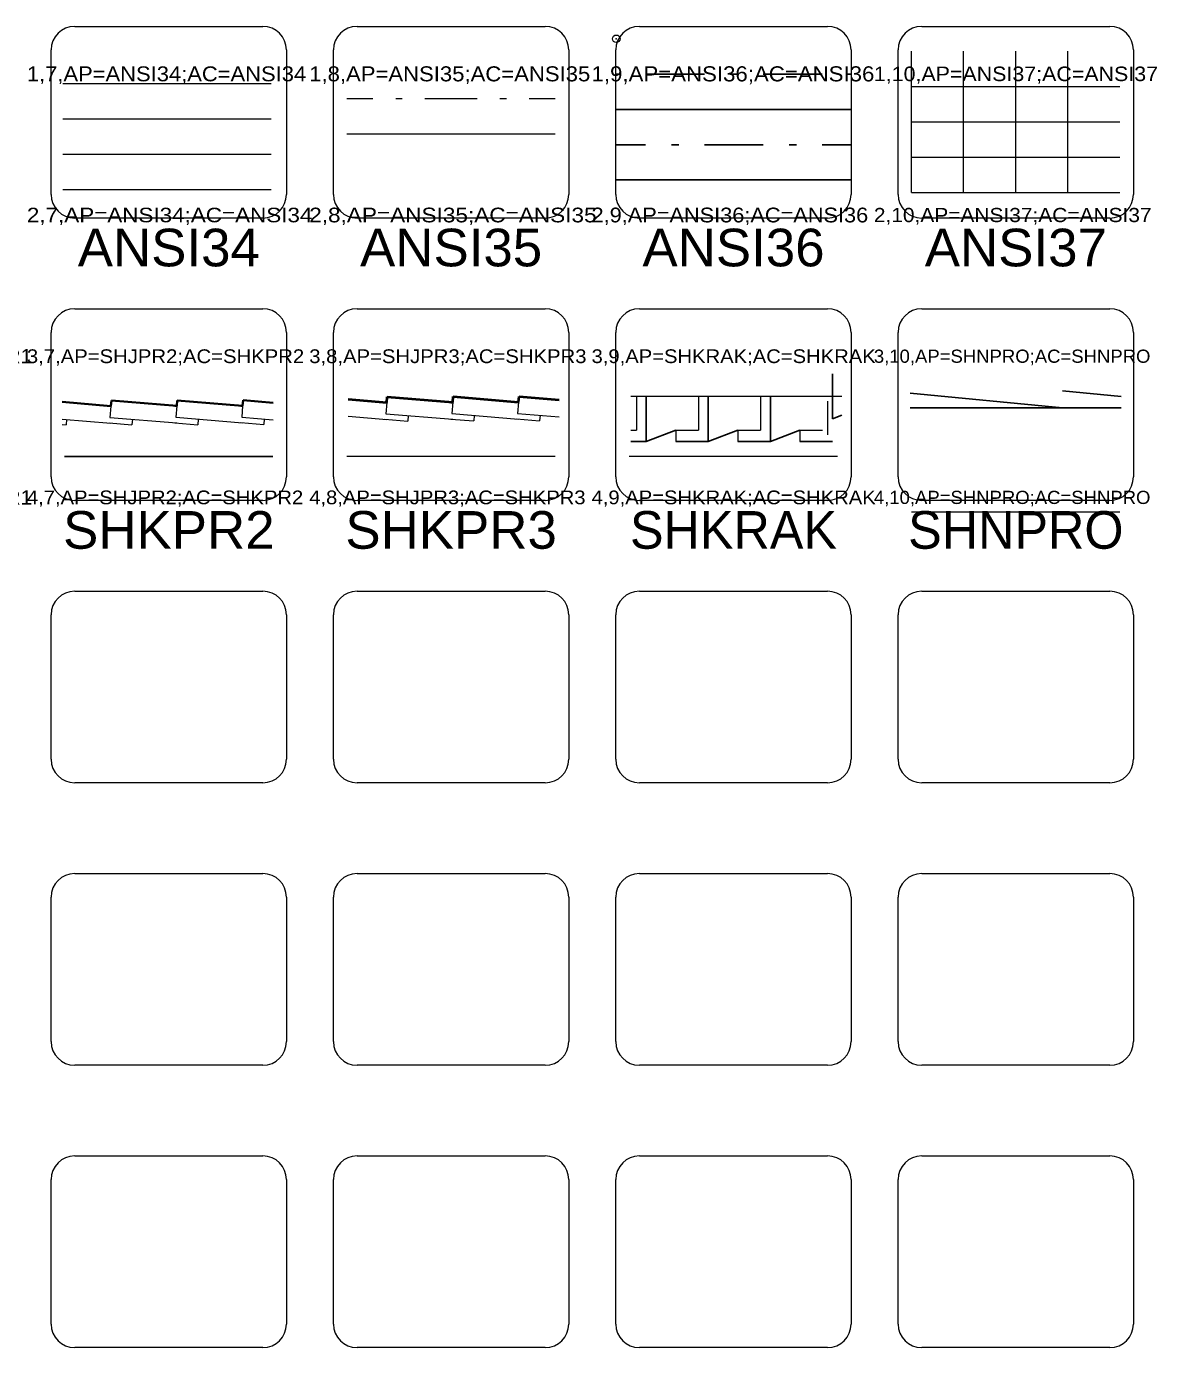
# Model space of a CAD drawing. Extents: x 95935 to 95946.4, y 95971.2 to 95974.7.
# Drawn here: x 95938.633 to 95941.029, y 95971.925 to 95974.732 of the extents above; entities that cross this region are included whole.
import ezdxf
from ezdxf.enums import TextEntityAlignment as Align

# ---------------------------------------------------------------- set-up
doc = ezdxf.new("R2010")
doc.units = 0
doc.header["$LTSCALE"] = 0.032
doc.header["$PDMODE"] = 32
doc.header["$PDSIZE"] = 0.016
for name, color, linetype, lineweight in [('1', 7, 'Continuous', 13), ('25', 7, 'Continuous', 13), ('6', 7, 'Continuous', 13), ('63', 7, 'Continuous', 13)]:
    doc.layers.add(name, color=color, linetype=linetype, lineweight=lineweight)
doc.layers.add('20', color=7, linetype='Continuous')

msp = doc.modelspace()

# ---------------------------------------------------------------- linework, layer by layer
at = {"layer": '1'}
for p, q in [((95938.7357, 95974.7318), (95939.1357, 95974.7318)), ((95939.3357, 95974.7318), (95939.7357, 95974.7318)), ((95939.9357, 95974.7318), (95940.3357, 95974.7318)), ((95940.5357, 95974.7318), (95940.9357, 95974.7318)), ((95938.6857, 95974.3747), (95938.6857, 95974.6818)), ((95939.1857, 95974.6818), (95939.1857, 95974.3747)), ((95939.2857, 95974.3747), (95939.2857, 95974.6818)), ((95939.7857, 95974.6818), (95939.7857, 95974.3747)), ((95939.8857, 95974.3747), (95939.8857, 95974.6818)), ((95940.3857, 95974.6818), (95940.3857, 95974.3747)), ((95940.4857, 95974.3747), (95940.4857, 95974.6818)), ((95940.9857, 95974.6818), (95940.9857, 95974.3747)), ((95939.1357, 95974.3247), (95938.7357, 95974.3247)), ((95939.7357, 95974.3247), (95939.3357, 95974.3247)), ((95940.3357, 95974.3247), (95939.9357, 95974.3247)), ((95940.9357, 95974.3247), (95940.5357, 95974.3247)), ((95938.7357, 95974.1318), (95939.1357, 95974.1318)), ((95939.3357, 95974.1318), (95939.7357, 95974.1318)), ((95939.9357, 95974.1318), (95940.3357, 95974.1318)), ((95940.5357, 95974.1318), (95940.9357, 95974.1318)), ((95938.6857, 95973.7747), (95938.6857, 95974.0818)), ((95939.1857, 95974.0818), (95939.1857, 95973.7747)), ((95939.2857, 95973.7747), (95939.2857, 95974.0818)), ((95939.7857, 95974.0818), (95939.7857, 95973.7747)), ((95939.8857, 95973.7747), (95939.8857, 95974.0818)), ((95940.3857, 95974.0818), (95940.3857, 95973.7747)), ((95940.4857, 95973.7747), (95940.4857, 95974.0818)), ((95940.9857, 95974.0818), (95940.9857, 95973.7747)), ((95939.1357, 95973.7247), (95938.7357, 95973.7247)), ((95939.7357, 95973.7247), (95939.3357, 95973.7247)), ((95940.3357, 95973.7247), (95939.9357, 95973.7247)), ((95940.9357, 95973.7247), (95940.5357, 95973.7247)), ((95938.7357, 95973.5318), (95939.1357, 95973.5318)), ((95939.3357, 95973.5318), (95939.7357, 95973.5318)), ((95939.9357, 95973.5318), (95940.3357, 95973.5318)), ((95940.5357, 95973.5318), (95940.9357, 95973.5318)), ((95938.6857, 95973.1747), (95938.6857, 95973.4818)), ((95939.1857, 95973.4818), (95939.1857, 95973.1747)), ((95939.2857, 95973.1747), (95939.2857, 95973.4818)), ((95939.7857, 95973.4818), (95939.7857, 95973.1747)), ((95939.8857, 95973.1747), (95939.8857, 95973.4818)), ((95940.3857, 95973.4818), (95940.3857, 95973.1747)), ((95940.4857, 95973.1747), (95940.4857, 95973.4818)), ((95940.9857, 95973.4818), (95940.9857, 95973.1747)), ((95939.1357, 95973.1247), (95938.7357, 95973.1247)), ((95939.7357, 95973.1247), (95939.3357, 95973.1247)), ((95940.3357, 95973.1247), (95939.9357, 95973.1247)), ((95940.9357, 95973.1247), (95940.5357, 95973.1247)), ((95938.7357, 95972.9318), (95939.1357, 95972.9318)), ((95939.3357, 95972.9318), (95939.7357, 95972.9318)), ((95939.9357, 95972.9318), (95940.3357, 95972.9318)), ((95940.5357, 95972.9318), (95940.9357, 95972.9318)), ((95938.6857, 95972.5747), (95938.6857, 95972.8818)), ((95939.1857, 95972.8818), (95939.1857, 95972.5747)), ((95939.2857, 95972.5747), (95939.2857, 95972.8818)), ((95939.7857, 95972.8818), (95939.7857, 95972.5747)), ((95939.8857, 95972.5747), (95939.8857, 95972.8818)), ((95940.3857, 95972.8818), (95940.3857, 95972.5747)), ((95940.4857, 95972.5747), (95940.4857, 95972.8818)), ((95940.9857, 95972.8818), (95940.9857, 95972.5747)), ((95939.1357, 95972.5247), (95938.7357, 95972.5247)), ((95939.7357, 95972.5247), (95939.3357, 95972.5247)), ((95940.3357, 95972.5247), (95939.9357, 95972.5247)), ((95940.9357, 95972.5247), (95940.5357, 95972.5247)), ((95938.7357, 95972.3318), (95939.1357, 95972.3318)), ((95939.3357, 95972.3318), (95939.7357, 95972.3318)), ((95939.9357, 95972.3318), (95940.3357, 95972.3318)), ((95940.5357, 95972.3318), (95940.9357, 95972.3318)), ((95938.6857, 95971.9747), (95938.6857, 95972.2818)), ((95939.1857, 95972.2818), (95939.1857, 95971.9747)), ((95939.2857, 95971.9747), (95939.2857, 95972.2818)), ((95939.7857, 95972.2818), (95939.7857, 95971.9747)), ((95939.8857, 95971.9747), (95939.8857, 95972.2818)), ((95940.3857, 95972.2818), (95940.3857, 95971.9747)), ((95940.4857, 95971.9747), (95940.4857, 95972.2818)), ((95940.9857, 95972.2818), (95940.9857, 95971.9747)), ((95939.1357, 95971.9247), (95938.7357, 95971.9247)), ((95939.7357, 95971.9247), (95939.3357, 95971.9247)), ((95940.3357, 95971.9247), (95939.9357, 95971.9247)), ((95940.9357, 95971.9247), (95940.5357, 95971.9247))]:
    msp.add_line(p, q, dxfattribs=at)
for centre, start, end in [((95938.7357, 95974.6818), 90, 180), ((95939.1357, 95974.6818), 0, 90), ((95939.3357, 95974.6818), 90, 180), ((95939.7357, 95974.6818), 0, 90), ((95939.9357, 95974.6818), 90, 180), ((95940.3357, 95974.6818), 0, 90), ((95940.5357, 95974.6818), 90, 180), ((95940.9357, 95974.6818), 0, 90), ((95938.7357, 95974.3747), 180, 270), ((95939.1357, 95974.3747), 270, 0), ((95939.3357, 95974.3747), 180, 270), ((95939.7357, 95974.3747), 270, 0), ((95939.9357, 95974.3747), 180, 270), ((95940.3357, 95974.3747), 270, 0), ((95940.5357, 95974.3747), 180, 270), ((95940.9357, 95974.3747), 270, 0), ((95938.7357, 95974.0818), 90, 180), ((95939.1357, 95974.0818), 0, 90), ((95939.3357, 95974.0818), 90, 180), ((95939.7357, 95974.0818), 0, 90), ((95939.9357, 95974.0818), 90, 180), ((95940.3357, 95974.0818), 0, 90), ((95940.5357, 95974.0818), 90, 180), ((95940.9357, 95974.0818), 0, 90), ((95938.7357, 95973.7747), 180, 270), ((95939.1357, 95973.7747), 270, 0), ((95939.3357, 95973.7747), 180, 270), ((95939.7357, 95973.7747), 270, 0), ((95939.9357, 95973.7747), 180, 270), ((95940.3357, 95973.7747), 270, 0), ((95940.5357, 95973.7747), 180, 270), ((95940.9357, 95973.7747), 270, 0), ((95938.7357, 95973.4818), 90, 180), ((95939.1357, 95973.4818), 0, 90), ((95939.3357, 95973.4818), 90, 180), ((95939.7357, 95973.4818), 0, 90), ((95939.9357, 95973.4818), 90, 180), ((95940.3357, 95973.4818), 0, 90), ((95940.5357, 95973.4818), 90, 180), ((95940.9357, 95973.4818), 0, 90), ((95938.7357, 95973.1747), 180, 270), ((95939.1357, 95973.1747), 270, 0), ((95939.3357, 95973.1747), 180, 270), ((95939.7357, 95973.1747), 270, 0), ((95939.9357, 95973.1747), 180, 270), ((95940.3357, 95973.1747), 270, 0), ((95940.5357, 95973.1747), 180, 270), ((95940.9357, 95973.1747), 270, 0), ((95938.7357, 95972.8818), 90, 180), ((95939.1357, 95972.8818), 0, 90), ((95939.3357, 95972.8818), 90, 180), ((95939.7357, 95972.8818), 0, 90), ((95939.9357, 95972.8818), 90, 180), ((95940.3357, 95972.8818), 0, 90), ((95940.5357, 95972.8818), 90, 180), ((95940.9357, 95972.8818), 0, 90), ((95938.7357, 95972.5747), 180, 270), ((95939.1357, 95972.5747), 270, 0), ((95939.3357, 95972.5747), 180, 270), ((95939.7357, 95972.5747), 270, 0), ((95939.9357, 95972.5747), 180, 270), ((95940.3357, 95972.5747), 270, 0), ((95940.5357, 95972.5747), 180, 270), ((95940.9357, 95972.5747), 270, 0), ((95938.7357, 95972.2818), 90, 180), ((95939.1357, 95972.2818), 0, 90), ((95939.3357, 95972.2818), 90, 180), ((95939.7357, 95972.2818), 0, 90), ((95939.9357, 95972.2818), 90, 180), ((95940.3357, 95972.2818), 0, 90), ((95940.5357, 95972.2818), 90, 180), ((95940.9357, 95972.2818), 0, 90), ((95938.7357, 95971.9747), 180, 270), ((95939.1357, 95971.9747), 270, 0), ((95939.3357, 95971.9747), 180, 270), ((95939.7357, 95971.9747), 270, 0), ((95939.9357, 95971.9747), 180, 270), ((95940.3357, 95971.9747), 270, 0), ((95940.5357, 95971.9747), 180, 270), ((95940.9357, 95971.9747), 270, 0)]:
    msp.add_arc(centre, 0.05, start, end, dxfattribs=at)
at = {"layer": '25'}
for p, q in [((95939.1569, 95973.8178), (95938.7141, 95973.8178)), ((95938.7141, 95973.8178), (95939.1569, 95973.8178)), ((95939.7569, 95973.8178), (95939.3141, 95973.8178)), ((95940.3569, 95973.8178), (95939.9141, 95973.8178)), ((95940.9569, 95973.6997), (95940.5141, 95973.6997))]:
    msp.add_line(p, q, dxfattribs=at)
at = {"layer": '6'}
for p, q in [((95940.5141, 95974.379), (95940.5141, 95974.679)), ((95940.6248, 95974.379), (95940.6248, 95974.679)), ((95940.7355, 95974.379), (95940.7355, 95974.679)), ((95940.8462, 95974.379), (95940.8462, 95974.679)), ((95938.7102, 95974.6103), (95939.153, 95974.6103)), ((95940.5141, 95974.604), (95940.9569, 95974.604)), ((95939.3141, 95974.5784), (95939.3694, 95974.5784)), ((95939.4179, 95974.5784), (95939.4317, 95974.5784)), ((95939.4801, 95974.5784), (95939.5908, 95974.5784)), ((95939.6393, 95974.5784), (95939.6531, 95974.5784)), ((95939.7015, 95974.5784), (95939.7569, 95974.5784)), ((95938.7102, 95974.5353), (95939.153, 95974.5353)), ((95940.5141, 95974.529), (95940.9569, 95974.529)), ((95939.3141, 95974.5034), (95939.7569, 95974.5034)), ((95938.7102, 95974.4603), (95939.153, 95974.4603)), ((95940.5141, 95974.454), (95940.9569, 95974.454)), ((95938.7102, 95974.3853), (95939.153, 95974.3853)), ((95940.5141, 95974.379), (95940.9569, 95974.379)), ((95939.9175, 95973.9462), (95940.0133, 95973.9462)), ((95939.9295, 95973.9462), (95939.9295, 95973.8742)), ((95940.0133, 95973.9462), (95940.1451, 95973.9462)), ((95940.0613, 95973.9462), (95940.0613, 95973.8742)), ((95940.1451, 95973.9462), (95940.2769, 95973.9462)), ((95940.1931, 95973.9462), (95940.1931, 95973.8742)), ((95940.2769, 95973.9462), (95940.3662, 95973.9462)), ((95940.3355, 95973.9357), (95940.3355, 95973.8637)), ((95938.8127, 95973.9251), (95938.8107, 95973.9011)), ((95938.9527, 95973.9254), (95938.9507, 95973.9014)), ((95939.0927, 95973.9257), (95939.0907, 95973.9017)), ((95939.399, 95973.933), (95939.397, 95973.909)), ((95939.397, 95973.909), (95939.539, 95973.8972)), ((95939.539, 95973.9333), (95939.537, 95973.9093)), ((95939.537, 95973.9093), (95939.679, 95973.8975)), ((95939.679, 95973.9336), (95939.677, 95973.9096)), ((95939.677, 95973.9096), (95939.7655, 95973.9022)), ((95938.7088, 95973.8976), (95938.8127, 95973.889)), ((95938.7088, 95973.8857), (95938.7174, 95973.885)), ((95938.7184, 95973.8969), (95938.7174, 95973.885)), ((95938.8087, 95973.8893), (95938.8574, 95973.8853)), ((95938.8107, 95973.9011), (95938.9527, 95973.8893)), ((95938.8584, 95973.8972), (95938.8574, 95973.8853)), ((95938.9487, 95973.8896), (95938.9974, 95973.8856)), ((95938.9507, 95973.9014), (95939.0927, 95973.8896)), ((95938.9984, 95973.8975), (95938.9974, 95973.8856)), ((95939.0887, 95973.8899), (95939.1374, 95973.8859)), ((95939.0907, 95973.9017), (95939.1575, 95973.8961)), ((95939.1384, 95973.8978), (95939.1374, 95973.8859)), ((95939.3168, 95973.9037), (95939.399, 95973.8969)), ((95939.395, 95973.8972), (95939.4437, 95973.8932)), ((95939.4447, 95973.9051), (95939.4437, 95973.8932)), ((95939.535, 95973.8975), (95939.5837, 95973.8935)), ((95939.5847, 95973.9054), (95939.5837, 95973.8935)), ((95939.675, 95973.8978), (95939.7237, 95973.8938)), ((95939.7247, 95973.9057), (95939.7237, 95973.8938)), ((95939.9175, 95973.8742), (95939.9295, 95973.8742)), ((95940.0133, 95973.8742), (95940.0613, 95973.8742)), ((95940.0133, 95973.8742), (95940.0133, 95973.8502)), ((95940.1451, 95973.8742), (95940.1931, 95973.8742)), ((95940.1451, 95973.8742), (95940.1451, 95973.8502)), ((95940.2769, 95973.8742), (95940.3249, 95973.8742)), ((95940.2769, 95973.8742), (95940.2769, 95973.8502))]:
    msp.add_line(p, q, dxfattribs=at)
at = {"layer": '6', "lineweight": 25}
for p, q in [((95939.8944, 95974.6305), (95939.8866, 95974.6305)), ((95939.9491, 95974.6305), (95940.0741, 95974.6305)), ((95940.1288, 95974.6305), (95940.1444, 95974.6305)), ((95940.1991, 95974.6305), (95940.3241, 95974.6305)), ((95940.3788, 95974.6305), (95940.3866, 95974.6305)), ((95939.8866, 95974.5555), (95940.3866, 95974.5555)), ((95939.8866, 95974.4805), (95939.9491, 95974.4805)), ((95940.0038, 95974.4805), (95940.0194, 95974.4805)), ((95940.0741, 95974.4805), (95940.1991, 95974.4805)), ((95940.2538, 95974.4805), (95940.2694, 95974.4805)), ((95940.3241, 95974.4805), (95940.3866, 95974.4805)), ((95939.8866, 95974.4055), (95940.3866, 95974.4055)), ((95940.3459, 95973.9937), (95940.3459, 95973.8977)), ((95940.0823, 95973.9462), (95940.0823, 95973.8502)), ((95940.2141, 95973.9462), (95940.2141, 95973.8502)), ((95940.511, 95973.9528), (95940.8349, 95973.9217)), ((95940.8349, 95973.9577), (95940.9597, 95973.9457)), ((95940.511, 95973.9217), (95940.9597, 95973.9217)), ((95940.3459, 95973.8977), (95940.3662, 95973.9055)), ((95940.0823, 95973.8502), (95940.1451, 95973.8742)), ((95940.2141, 95973.8502), (95940.2769, 95973.8742)), ((95939.9175, 95973.8502), (95939.9505, 95973.8502)), ((95940.0133, 95973.8502), (95940.0823, 95973.8502)), ((95940.1451, 95973.8502), (95940.2141, 95973.8502)), ((95940.2769, 95973.8502), (95940.3459, 95973.8502))]:
    msp.add_line(p, q, dxfattribs=at)
at = {"layer": '6', "lineweight": 35}
for p, q in [((95938.8127, 95973.9251), (95938.8137, 95973.937)), ((95938.8137, 95973.937), (95938.9527, 95973.9254)), ((95938.9527, 95973.9254), (95938.9537, 95973.9373)), ((95938.9537, 95973.9373), (95939.0927, 95973.9257)), ((95939.0927, 95973.9257), (95939.0937, 95973.9376)), ((95939.0937, 95973.9376), (95939.1575, 95973.9323)), ((95938.7088, 95973.9338), (95938.8127, 95973.9251)), ((95938.8087, 95973.9254), (95938.8127, 95973.9251)), ((95938.9487, 95973.9257), (95938.9527, 95973.9254)), ((95939.0887, 95973.926), (95939.0927, 95973.9257))]:
    msp.add_line(p, q, dxfattribs=at)
at = {"layer": '6', "lineweight": 40}
for p, q in [((95939.3168, 95973.9399), (95939.399, 95973.933)), ((95939.399, 95973.933), (95939.4, 95973.9449)), ((95939.4, 95973.9449), (95939.539, 95973.9333)), ((95939.539, 95973.9333), (95939.54, 95973.9452)), ((95939.54, 95973.9452), (95939.679, 95973.9336)), ((95939.679, 95973.9336), (95939.68, 95973.9455)), ((95939.68, 95973.9455), (95939.7655, 95973.9384)), ((95939.395, 95973.9333), (95939.399, 95973.933)), ((95939.535, 95973.9336), (95939.539, 95973.9333)), ((95939.675, 95973.9339), (95939.679, 95973.9336))]:
    msp.add_line(p, q, dxfattribs=at)
at = {"layer": '6', "lineweight": 25}
msp.add_lwpolyline([(95939.9505, 95973.9462), (95939.9505, 95973.8502), (95940.0133, 95973.8742)], dxfattribs=at)
at = {"layer": '6'}
msp.add_point((95939.8866, 95974.7055), dxfattribs=at)

# ---------------------------------------------------------------- texts
at = {"layer": '20', "width": 1.05}
for s, p in [('ANSI34', (95938.9358, 95974.222)), ('ANSI35', (95939.5357, 95974.222)), ('ANSI36', (95940.1358, 95974.222)), ('ANSI37', (95940.7358, 95974.222)), ('SHKPR2', (95938.9358, 95973.622)), ('SHKPR3', (95939.5357, 95973.622))]:
    msp.add_text(s, height=0.08, dxfattribs=at).set_placement(p, align=Align.CENTER)
at = {"layer": '20'}
for s, p in [('SHKRAK', (95940.1358, 95973.622)), ('SHNPRO', (95940.7358, 95973.622))]:
    msp.add_text(s, height=0.08, dxfattribs=at).set_placement(p, align=Align.CENTER)
at = {"layer": '63'}
for s, height, width, p in [('1,7,AP=ANSI34;AC=ANSI34', 0.0317, 1.1, (95938.6341, 95974.6152)), ('1,8,AP=ANSI35;AC=ANSI35', 0.0319, 1.1, (95939.2341, 95974.6151)), ('1,9,AP=ANSI36;AC=ANSI36', 0.0321, 1.1, (95939.8341, 95974.615)), ('1,10,AP=ANSI37;AC=ANSI37', 0.0309, 1.1, (95940.4341, 95974.6156)), ('2,7,AP=ANSI34;AC=ANSI34', 0.031, 1.15, (95938.6341, 95974.3156)), ('2,8,AP=ANSI35;AC=ANSI35', 0.0312, 1.15, (95939.2341, 95974.3155)), ('2,9,AP=ANSI36;AC=ANSI36', 0.0314, 1.1, (95939.8341, 95974.3154)), ('2,10,AP=ANSI37;AC=ANSI37', 0.0302, 1.1, (95940.4341, 95974.316)), ('3,6,AP=SHJPR1;AC=SHKPR1', 0.0304, 1.1, (95938.0341, 95974.0159)), ('3,7,AP=SHJPR2;AC=SHKPR2', 0.0293, 1.1, (95938.6341, 95974.0164)), ('3,8,AP=SHJPR3;AC=SHKPR3', 0.0293, 1.1, (95939.2341, 95974.0164)), ('3,9,AP=SHKRAK;AC=SHKRAK', 0.0292, 1.1, (95939.8341, 95974.0165)), ('3,10,AP=SHNPRO;AC=SHNPRO', 0.028, 1.05, (95940.4341, 95974.0171)), ('4,6,AP=SHJPR1;AC=SHKPR1', 0.0304, 1.1, (95938.0341, 95973.7159)), ('4,7,AP=SHJPR2;AC=SHKPR2', 0.0292, 1.1, (95938.6341, 95973.7165)), ('4,8,AP=SHJPR3;AC=SHKPR3', 0.0292, 1.1, (95939.2341, 95973.7165)), ('4,9,AP=SHKRAK;AC=SHKRAK', 0.0292, 1.1, (95939.8341, 95973.7165)), ('4,10,AP=SHNPRO;AC=SHNPRO', 0.028, 1.05, (95940.4341, 95973.7171))]:
    msp.add_text(s, height=height, dxfattribs=dict(at, width=width)).set_placement(p)

doc.saveas('drawing.dxf')
